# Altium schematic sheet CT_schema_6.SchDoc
size 205 x 258 mm
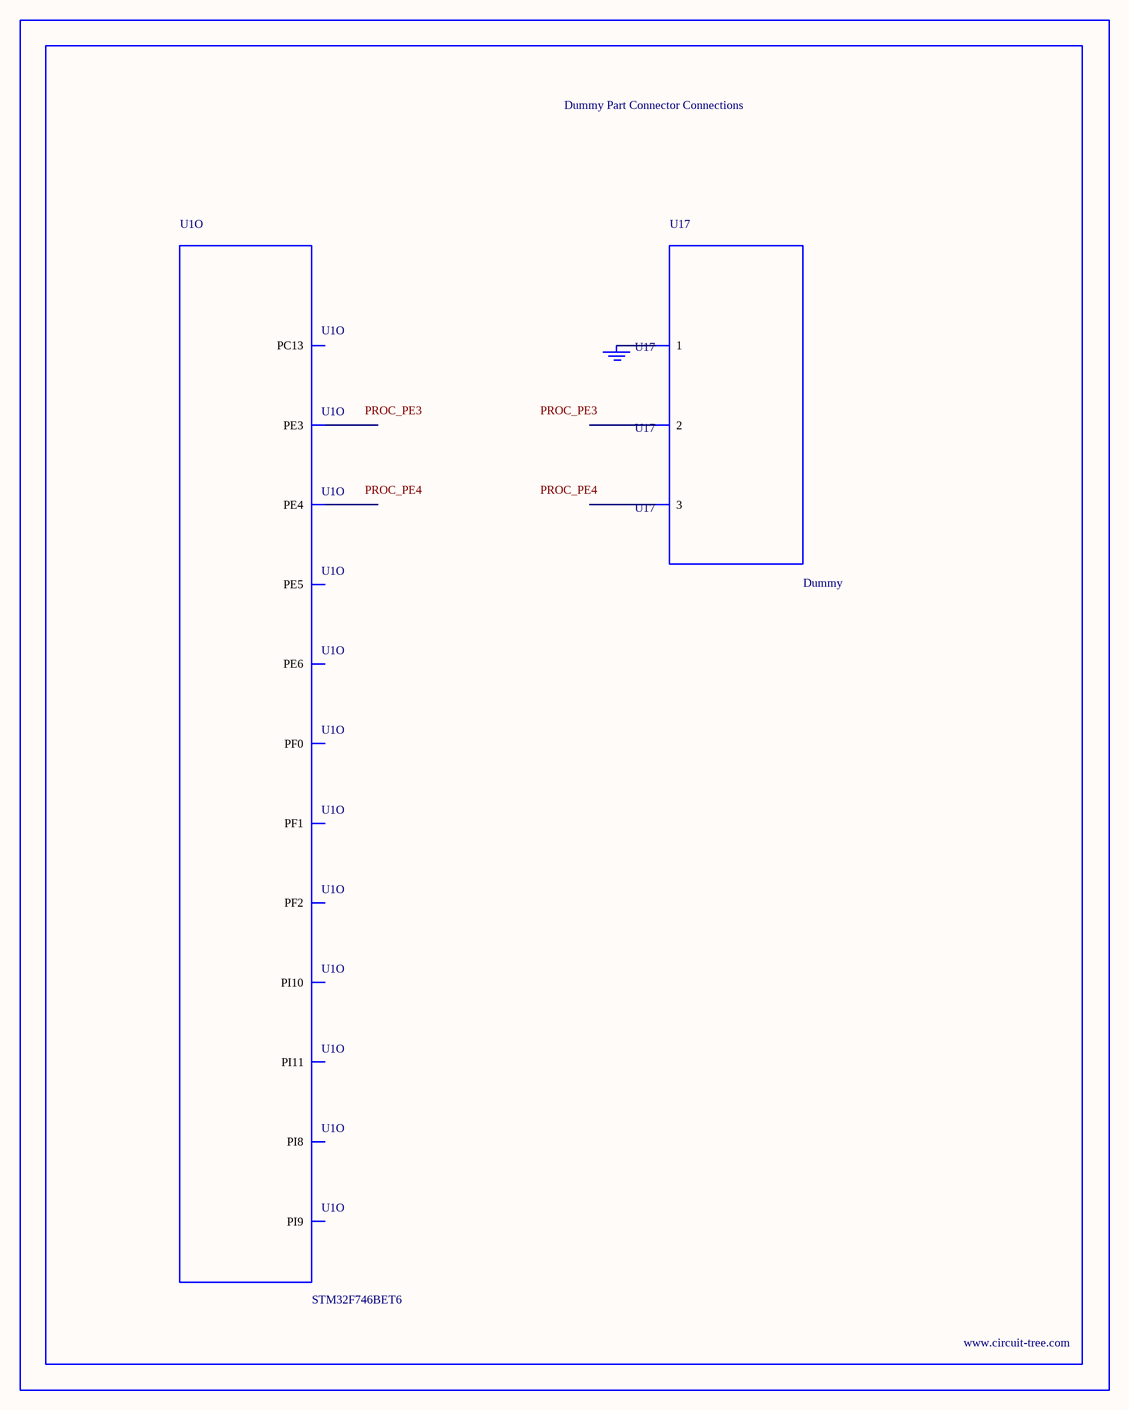
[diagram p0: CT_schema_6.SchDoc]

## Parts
BORDER5  (no value)
GND_INSTANCE_5_0  (no value)
U1  STM32F746BET6  [LQFP208]  (part O of 15)
U17  Dummy  [DUMMY_PACKAGE_194]

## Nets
NetGND_INSTANCE_5_0_0: GND_INSTANCE_5_0.0(GND) U17.1

Not connected (* = marked no-connect by the designer): U1 2(PE3) 3(PE4) 4(PE5) 5(PE6) 7(PI8) 8(PC13) 11(PI9) 12(PI10) 13(PI11) 16(PF0) 17(PF1) 18(PF2); U17 2 3

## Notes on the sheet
- Labels drawn without touching a wire or pin: PROC_PE3, PROC_PE4

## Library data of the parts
BORDER5 = BORDER_PAGE5
GND_INSTANCE_5_0 = GND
